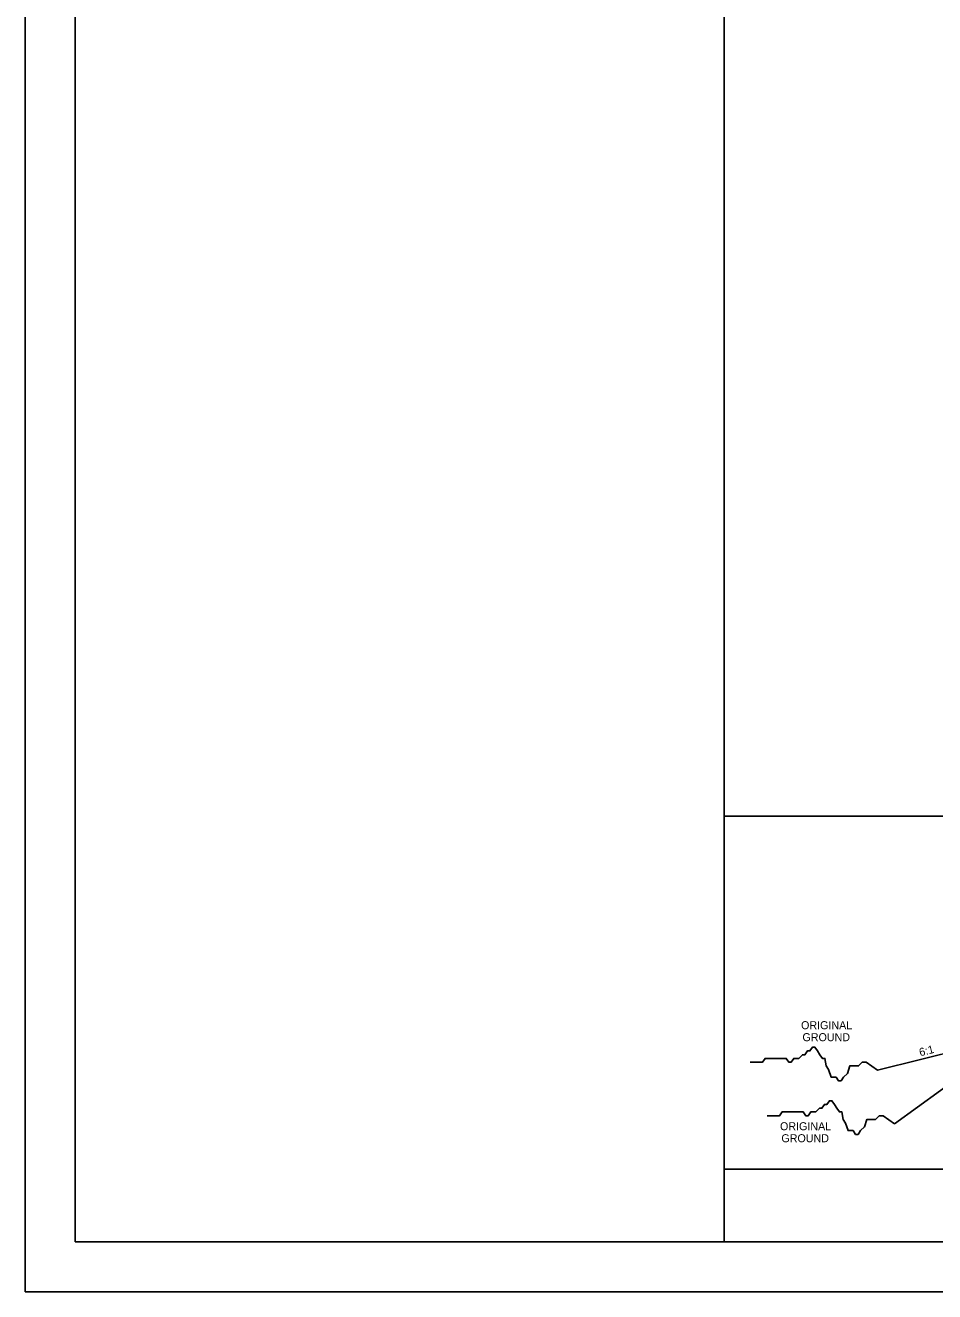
# Model space of a CAD drawing. Extents: x 1636954 to 1644154, y 841334 to 845582.
# Drawn here: x 1636954 to 1637865, y 841334 to 842602 of the extents above; entities that cross this region are included whole.
import ezdxf

# ---------------------------------------------------------------- set-up
doc = ezdxf.new("R2010")
doc.units = 0
for name, color, linetype in [('Prop Dimension Text', 7, 'Continuous'), ('Prop PHM Legend CELL', 7, 'Continuous'), ('Scratch_Level_1', 7, 'Continuous'), ('Sheet Plan And Profile CELL', 7, 'Continuous'), ('Typical Hinge Slope Interstate CELL', 7, 'Continuous')]:
    doc.layers.add(name, color=color, linetype=linetype)

msp = doc.modelspace()

# ---------------------------------------------------------------- linework, layer by layer
at = {"layer": 'Prop PHM Legend CELL'}
msp.add_line((1637654.2, 841456.6), (1640851.7, 841456.6), dxfattribs=at)
msp.add_lwpolyline([(1637654.2, 841810.2), (1639599.4, 841810.2), (1639599.4, 841383.9), (1637654.2, 841383.9)], close=True, dxfattribs=at)
at = {"layer": 'Scratch_Level_1'}
msp.add_lwpolyline([(1636954.2, 841333.9), (1636954.2, 844733.9), (1644154.2, 844733.9), (1644154.2, 841333.9)], close=True, dxfattribs=at)
at = {"layer": 'Sheet Plan And Profile CELL'}
msp.add_lwpolyline([(1637004.2, 841383.9), (1637004.2, 844683.9), (1644104.2, 844683.9), (1644104.2, 841383.9)], close=True, dxfattribs=at)
msp.add_lwpolyline([(1637654.2, 844683.9), (1637654.2, 841383.9)], dxfattribs=at)
at = {"layer": 'Typical Hinge Slope Interstate CELL'}
for q in [(1637808, 841555.7), (1637825.1, 841502.1)]:
    msp.add_line((1637946.3, 841590.3), q, dxfattribs=at)
for points in [[(1637808, 841555.7), (1637796.5, 841563.8), (1637792.7, 841563.8), (1637789, 841560.1), (1637786.5, 841560.1), (1637782.7, 841560.1), (1637780.2, 841560.1), (1637777.8, 841552.6), (1637774, 841548.9), (1637771.5, 841545.1), (1637769, 841545.1), (1637766.5, 841548.9), (1637764, 841548.9), (1637761.5, 841548.9), (1637759, 841556.3), (1637756.5, 841560.1), (1637755.3, 841567.6), (1637752.8, 841567.6), (1637750.3, 841571.3), (1637747.8, 841575.1), (1637745.3, 841578.8), (1637742.8, 841578.8), (1637740.3, 841575.1), (1637737.8, 841575.1), (1637735.3, 841571.3), (1637732.8, 841571.3), (1637729.1, 841567.6), (1637726.6, 841567.6), (1637724.1, 841567.6), (1637721.6, 841563.8), (1637719.1, 841563.8), (1637716.6, 841567.6), (1637714.1, 841567.6), (1637711.6, 841567.6), (1637709.1, 841567.6), (1637706.6, 841567.6), (1637702.8, 841567.6), (1637699.1, 841567.6), (1637695.4, 841567.6), (1637692.9, 841563.8), (1637689.1, 841563.8), (1637685.4, 841563.8), (1637680.4, 841563.8)], [(1637825.1, 841502.1), (1637813.5, 841510.2), (1637809.7, 841510.2), (1637806, 841506.5), (1637803.5, 841506.5), (1637799.7, 841506.5), (1637797.3, 841506.5), (1637794.8, 841499), (1637791, 841495.2), (1637788.5, 841491.5), (1637786, 841491.5), (1637783.5, 841495.2), (1637781, 841495.2), (1637778.5, 841495.2), (1637776, 841502.7), (1637773.5, 841506.5), (1637772.3, 841514), (1637769.8, 841514), (1637767.3, 841517.7), (1637764.8, 841521.5), (1637762.3, 841525.2), (1637759.8, 841525.2), (1637757.3, 841521.5), (1637754.8, 841521.5), (1637752.3, 841517.7), (1637749.8, 841517.7), (1637746.1, 841514), (1637743.6, 841514), (1637741.1, 841514), (1637738.6, 841510.2), (1637736.1, 841510.2), (1637733.6, 841514), (1637731.1, 841514), (1637728.6, 841514), (1637726.1, 841514), (1637723.6, 841514), (1637719.8, 841514), (1637716.1, 841514), (1637712.4, 841514), (1637709.9, 841510.2), (1637706.1, 841510.2), (1637702.4, 841510.2), (1637697.4, 841510.2)]]:
    msp.add_lwpolyline(points, dxfattribs=at)

# ---------------------------------------------------------------- texts
at = {"layer": 'Prop Dimension Text'}
for s, p in [('ORIGINAL', (1637731.4, 841596.8)), ('GROUND', (1637732.8, 841584.8)), ('ORIGINAL', (1637710.3, 841495.6)), ('GROUND', (1637711.7, 841483.6))]:
    msp.add_text(s, height=8.02, dxfattribs=at).set_placement(p)
msp.add_text('6:1', height=8.02, rotation=14.0362, dxfattribs=at).set_placement((1637850.8, 841569.6))

doc.saveas('drawing.dxf')
